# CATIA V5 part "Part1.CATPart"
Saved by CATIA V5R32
Part number: Part1
Bounding box of the stored display mesh (mm): x -100 to 100, y -50 to 50, z 0 to 10
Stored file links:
  D:\PROJECTS\Project 2022\CATIA V5 6R 2022\Resources\Part Files\c16_catia_v5_6r2022_prt\Planer Joint-(Fig16-33)\Part1.CATPart
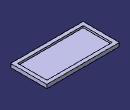
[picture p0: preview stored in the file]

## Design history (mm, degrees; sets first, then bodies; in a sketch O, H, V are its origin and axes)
Body1 (main body)
  Sketch1 on xy-plane, origin (0, 0, 0), H (1, 0, 0), V (0, 1, 0)
    line L1 (100, 50) -> (100, -50)
    line L2 (100, -50) -> (-100, -50)
    line L3 (-100, -50) -> (-100, 50)
    line L4 (-100, 50) -> (100, 50)
    line L5 (90, 40) -> (90, -40)
    line L6 (90, -40) -> (-90, -40)
    line L7 (-90, -40) -> (-90, 40)
    line L8 (-90, 40) -> (90, 40)
    length L4 = 200
    length L1 = 100
    length L8 = 180
    length L5 = 80
    vertical: L1 V, L3 V, L5 V, L7 V
    horizontal: L2 H, L4 H, L6 H, L8 H
    equidistance: L1 L3 O, L2 L4 O, L5 L7 O, L6 L8 O
  MultiPad1: profile Sketch1, domains (length 5; length 10)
